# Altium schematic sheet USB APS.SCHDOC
size A
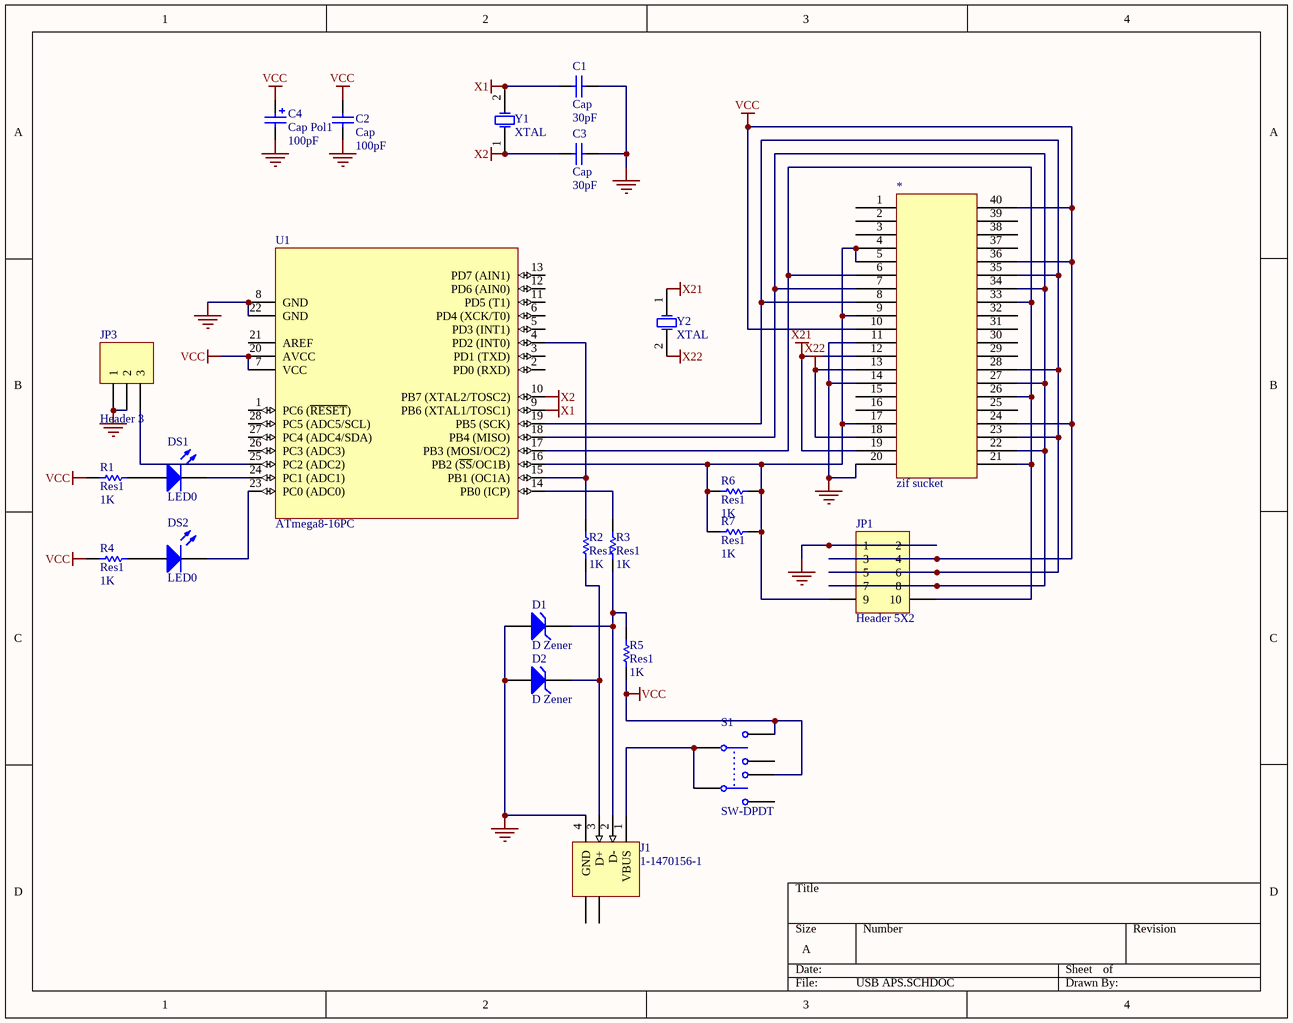
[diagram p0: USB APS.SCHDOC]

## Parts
*  zif sucket  [40P6]
C1  Cap  value 30pF  [RAD-0.1]
C2  Cap  value 100pF  [RAD-0.2]
C3  Cap  value 30pF  [RAD-0.1]
C4  Cap Pol1  value 100pF  [CAPPR3.5-8x5]
D1  D Zener  [DIODE-0.4]
D2  D Zener  [DIODE-0.4]
DS1  LED0  [LED3mm]
DS2  LED0  [LED3mm]
J1  1-1470156-1  [1-1470156]
JP1  Header 5X2  [HDR2X5]
JP3  Header 3  [HDR1X3]
R1  Res1  value 1K  [AXIAL-0.4]
R2  Res1  value 1K  [AXIAL-0.4]
R3  Res1  value 1K  [AXIAL-0.4]
R4  Res1  value 1K  [AXIAL-0.4]
R5  Res1  value 1K  [AXIAL-0.4]
R6  Res1  value 1K  [AXIAL-0.4]
R7  Res1  value 1K  [AXIAL-0.4]
S1  SW-DPDT  [DPDT-6]
U1  ATmega8-16PC  [28P3]
Y1  XTAL  [xtal - duplicate]
Y2  XTAL  [xtal - duplicate]

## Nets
GND: *.11 *.14 *.20 C1.2 C2.1 C3.2 C4.2 D1.1(A) D2.1(A) J1.4(GND) JP1.1 JP1.2 JP3.1 JP3.2 U1.8(GND) U1.22(GND)
VCC: *.10 *.24 *.36 *.40 C2.2 C4.1 JP1.3 JP1.4 R1.1 R4.1 R5.2 S1.2 S1.5 U1.7(VCC) U1.20(AVCC)
X1: C1.1 U1.9(PB6_(XTAL1/TOSC1)) Y1.2(OSC2)
X2: C3.1 U1.10(PB7_(XTAL2/TOSC2)) Y1.1(OSC1)
X21: *.12 *.19 Y2.1(OSC1)
X22: *.13 *.18 Y2.2(OSC2)
Net*_4: *.4 *.5 *.9 *.17 JP1.9 R6.1 R6.2 R7.1 R7.2 U1.16(PB2_(~{SS}/OC1B))
Net*_6: *.6 *.21 *.26 *.33 JP1.10 U1.17(PB3_(MOSI/OC2))
Net*_7: *.7 *.22 *.27 *.34 JP1.7 JP1.8 U1.18(PB4_(MISO))
Net*_8: *.8 *.23 *.28 *.35 JP1.5 JP1.6 U1.19(PB5_(SCK))
NetD1_2: D1.2(K) J1.2(D-) R3.1 R5.1
NetD2_2: D2.2(K) J1.3(D+) R2.1
NetDS1_1: DS1.1(A) R1.2
NetDS1_2: DS1.2(K) U1.24(PC1_(ADC1))
NetDS2_1: DS2.1(A) R4.2
NetDS2_2: DS2.2(K) U1.23(PC0_(ADC0))
NetJ1_1: J1.1(VBUS) S1.1 S1.4
NetJP3_3: JP3.3 U1.25(PC2_(ADC2))
NetR2_2: R2.2 U1.4(PD2_(INT0)) U1.15(PB1_(OC1A))
NetR3_2: R3.2 U1.14(PB0_(ICP))

Not connected (* = marked no-connect by the designer): * 1 2 3 15 16 25 29 30 31 32 37 38 39; J1 5(SHLD) 6(SHLD); S1 3 6; U1 1(PC6_(~{RESET})) 2(PD0_(RXD)) 3(PD1_(TXD)) 5(PD3_(INT1)) 6(PD4_(XCK/T0)) 11(PD5_(T1)) 12(PD6_(AIN0)) 13(PD7_(AIN1)) 21(AREF) 26(PC3_(ADC3)) 27(PC4_(ADC4/SDA)) 28(PC5_(ADC5/SCL))

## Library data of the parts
* = Component_1
C1-C3 = Cap: Capacitor
C4 = Cap Pol1: Polarized Capacitor (Radial)
D1 D2 = D Zener: Zener Diode
DS1 DS2 = LED0: Typical INFRARED GaAs LED
J1 = 1-1470156-1: USB 1.1, Right Angle, Thru-Hole, B Type, Receptacle, 4 Position, White; ContactMaterial: Phosphor Bronze; ContactPlating: Gold over Nickel; TerminationLength: 3.00mm [0.118in.]; PCB_Layout: Complies with manufacturer's recommendation.; DrillSize: Corresponds to nominal value.; PanelGround: Without
JP1 = Header 5X2: Header, 5-Pin, Dual row
JP3 = Header 3: Header, 3-Pin
R1-R7 = Res1: Resistor
S1 = SW-DPDT: Double-Pole, Double-Throw Switch
U1 = ATmega8-16PC: 8-Bit AVR Microcontroller with 8K Bytes of In-System Programmable Flash Memory; Package Information: Latest Revision: revB, Sep-2001
Y1 Y2 = XTAL: Crystal Oscillator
